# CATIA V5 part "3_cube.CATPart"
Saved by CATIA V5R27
Part number: 47065T245_T-Slotted Framing
Revision: ANY
Definition: UNKNOWN
Nomenclature: 47065T245_T-Slotted Framing
Source: Unknown
Bounding box of the stored display mesh (mm): x -3 to 38.1, y -3 to 38.1, z -3 to 38.1
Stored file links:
  \\triton.meca.polymtl.ca\usagers\zaoue\profiles\Desktop\varm_ass\structure prismatique\3_cube.CATPart
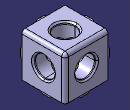
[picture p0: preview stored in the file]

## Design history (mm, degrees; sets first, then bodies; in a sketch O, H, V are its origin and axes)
Body1 "Revolve1" (main body)
Body2 "Mirror4"
Body3 "Mirror5"
Body4 "Chamfer1"
  Solid1: solid without history
  Sketch1 on face of Solid1, origin (0, 0, 0), H (1, 0, 0), V (0, 0, 1)
    line L1 (0, 38.1) -> (38.1, 38.1)
    line L2 (38.1, 38.1) -> (38.1, 0)
    line L3 (38.1, 0) -> (0, 0)
    line L4 (0, 0) -> (0, 38.1)
    distance L4 L2 = 38.1
    distance L1 L3 = 38.1
    horizontal: L1 H, L3 H
    vertical: L2 V, L4 V
    coincidence: L3 H, L4 V
  Pad1: profile Sketch1, direction (0, 1, 0), up to face of Solid1, deactivated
